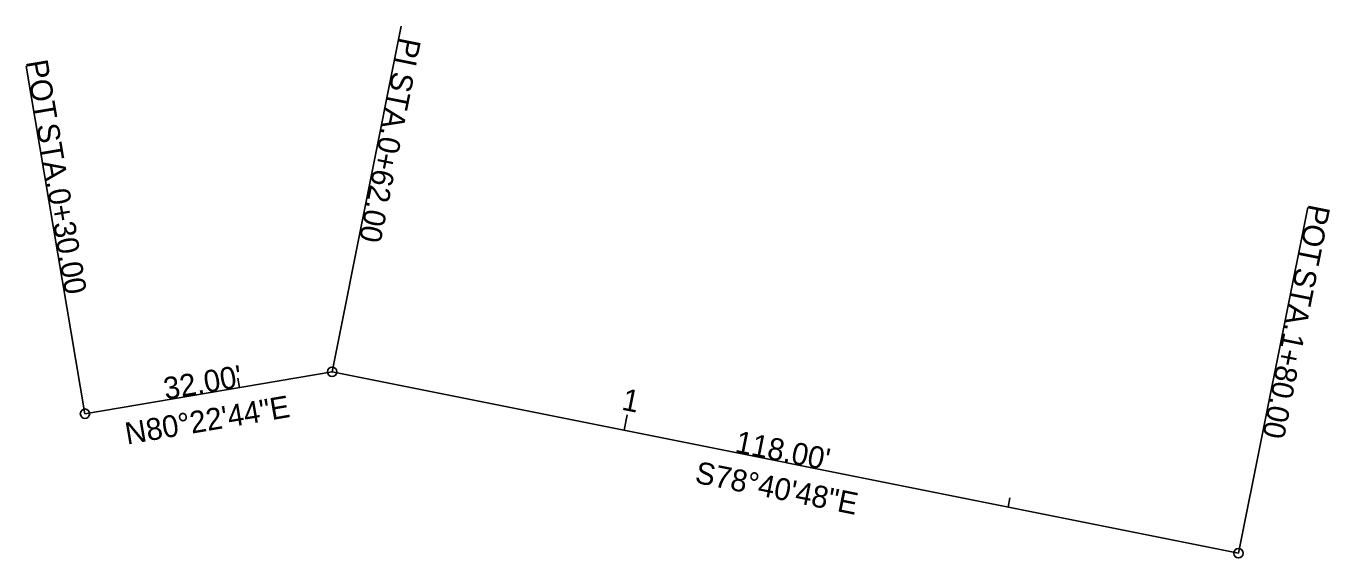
# Model space of a CAD drawing. Extents: x 2227447 to 2228402, y 680573 to 680795.
# Drawn here: x 2228235.5 to 2228402, y 680572.8 to 680640.7 of the extents above; entities that cross this region are included whole.
import ezdxf

# ---------------------------------------------------------------- set-up
doc = ezdxf.new("R2010")
doc.units = 0
for name, color, linetype in [('GE_P_Alignment', 7, 'Continuous'), ('GE_P_Alignment_100_Bearings', 7, 'Continuous'), ('GE_P_Alignment_100_Cardinal_Points', 7, 'Continuous'), ('GE_P_Alignment_100_Distances', 7, 'Continuous'), ('GE_P_Alignment_100_Stations', 7, 'Continuous')]:
    doc.layers.add(name, color=color, linetype=linetype)

msp = doc.modelspace()

# ---------------------------------------------------------------- linework, layer by layer
at = {"layer": 'GE_P_Alignment'}
for p, q in [((2228243.04, 680591.2), (2228274.59, 680596.55)), ((2228274.59, 680596.55), (2228390.29, 680573.39))]:
    msp.add_line(p, q, dxfattribs=at)
at = {"layer": 'GE_P_Alignment_100_Cardinal_Points'}
for p, q in [((2228274.59, 680596.55), (2228283.42, 680640.68)), ((2228243.04, 680591.2), (2228235.52, 680635.57)), ((2228390.29, 680573.39), (2228399.13, 680617.52))]:
    msp.add_line(p, q, dxfattribs=at)
for centre in [(2228274.59, 680596.55), (2228243.04, 680591.2), (2228390.29, 680573.39)]:
    msp.add_circle(centre, 0.6, dxfattribs=at)
at = {"layer": 'GE_P_Alignment_100_Stations'}
for p, q in [((2228262.76, 680594.55), (2228262.56, 680595.73)), ((2228311.85, 680589.09), (2228312.24, 680591.05)), ((2228360.88, 680579.28), (2228361.11, 680580.46))]:
    msp.add_line(p, q, dxfattribs=at)

# ---------------------------------------------------------------- texts
at = {"layer": 'GE_P_Alignment_100_Bearings'}
for s, rotation, p in [('N80°22\'44"E', 9.621, (2228248.41, 680587.25)), ('S78°40\'48"E', 348.68, (2228320.77, 680582.41))]:
    msp.add_text(s, height=2.8, rotation=rotation, dxfattribs=at).set_placement(p)
at = {"layer": 'GE_P_Alignment_100_Cardinal_Points'}
for s, rotation, p in [('PI', 258.68, (2228283.2, 680639.35)), ('POT', 279.621, (2228235.47, 680636.14)), (' STA. ', 258.68, (2228282.54, 680636.03)), (' STA. ', 279.621, (2228236.67, 680629.04)), ('0+62.00', 258.68, (2228280.68, 680626.76)), ('0+30.00', 279.621, (2228238.25, 680619.72)), ('POT', 258.68, (2228399.28, 680618.06)), (' STA. ', 258.68, (2228397.87, 680611)), ('1+80.00', 258.68, (2228396.01, 680601.73))]:
    msp.add_text(s, height=2.8, rotation=rotation, dxfattribs=at).set_placement(p)
at = {"layer": 'GE_P_Alignment_100_Distances'}
for s, rotation, p in [("32.00'", 9.621, (2228253.32, 680592.99)), ("118.00'", 348.68, (2228325.9, 680586.32))]:
    msp.add_text(s, height=2.8, rotation=rotation, dxfattribs=at).set_placement(p)
at = {"layer": 'GE_P_Alignment_100_Stations'}
msp.add_text('1', height=2.8, rotation=348.68, dxfattribs=at).set_placement((2228311.44, 680591.73))

doc.saveas('drawing.dxf')
